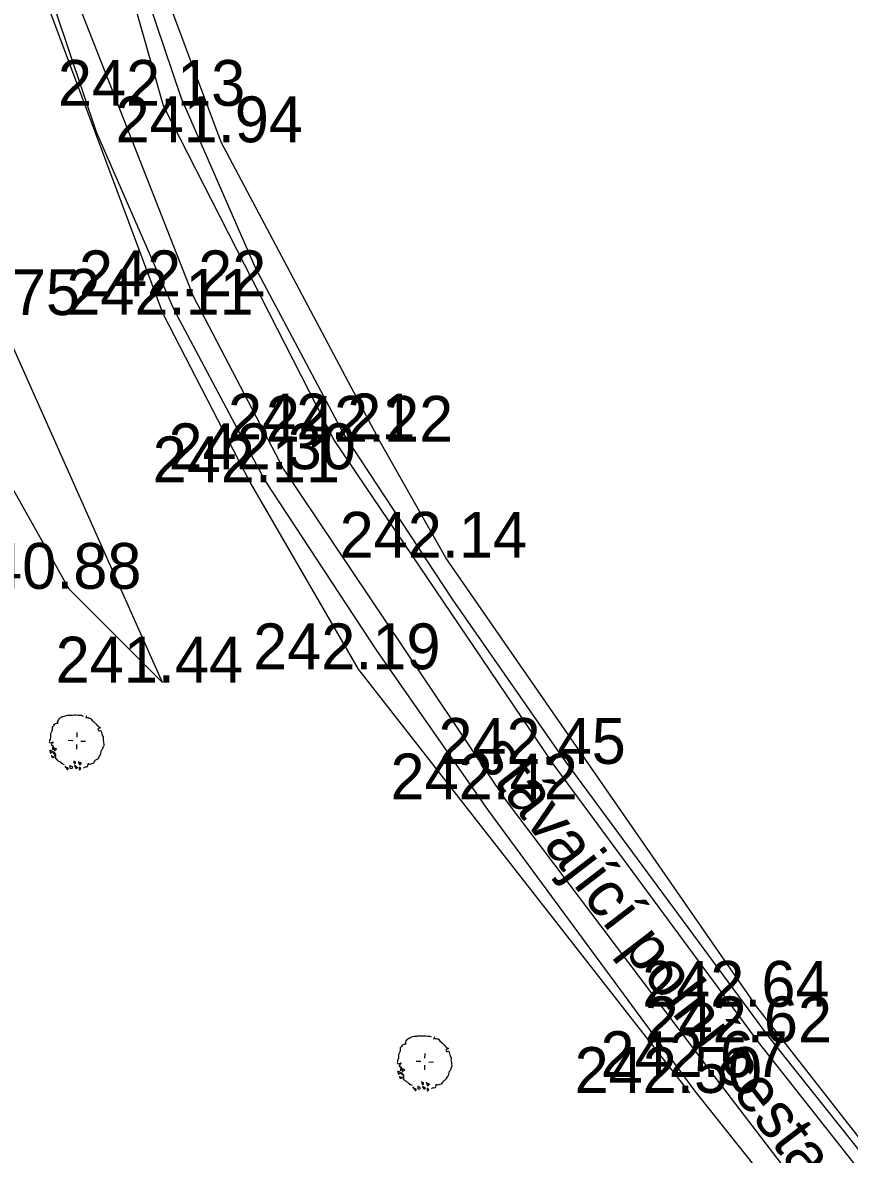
# Model space of a CAD drawing. Extents: x -601739 to -601440, y -1201912 to -1200862.
# Drawn here: x -601509.07 to -601472.98, y -1201685.45 to -1201636.06 of the extents above; entities that cross this region are included whole.
import ezdxf

# ---------------------------------------------------------------- set-up
doc = ezdxf.new("R2010")
doc.units = 0
for name, color, linetype in [('Hranice parcel', 7, 'Continuous'), ('u_hrany', 7, 'Continuous'), ('u_S0 02', 7, 'Continuous'), ('u_vysadba', 7, 'Continuous'), ('u_vyska', 7, 'Continuous')]:
    doc.layers.add(name, color=color, linetype=linetype)

msp = doc.modelspace()

# ---------------------------------------------------------------- linework, layer by layer
at = {"layer": 'Hranice parcel'}
for points in [[(-601518.5, -1201574.62), (-601510.22, -1201581.07), (-601510.94, -1201612.53), (-601510.72, -1201619.53), (-601510.05, -1201624.75), (-601508.24, -1201633.75), (-601505.86, -1201640.82), (-601502.47, -1201648.58), (-601498.5, -1201656.04), (-601493.62, -1201663.46), (-601488.75, -1201670.45), (-601479.72, -1201682.69), (-601461.88, -1201705.09), (-601445.87, -1201723.83)], [(-601460.43, -1201700.48), (-601476.54, -1201680.26), (-601485.5, -1201668.12), (-601490.31, -1201661.22), (-601495.06, -1201653.99), (-601498.9, -1201646.76), (-601502.13, -1201639.37), (-601504.35, -1201632.81), (-601505.66, -1201626.3)]]:
    msp.add_lwpolyline(points, dxfattribs=at)
at = {"layer": 'u_hrany'}
for points in [[(-601514.2, -1201569.51), (-601517.03, -1201570.93), (-601522.49, -1201584.67), (-601523.6, -1201596.8), (-601523.78, -1201607.28), (-601522.35, -1201622.38), (-601520.26, -1201632.29), (-601514.11, -1201648.21), (-601507.05, -1201660.77), (-601502.96, -1201664.86), (-601510.13, -1201648.82), (-601514.08, -1201638.6), (-601517, -1201627.14), (-601517.98, -1201618.06), (-601518.55, -1201594.5), (-601514.93, -1201583.59), (-601509.76, -1201580.82)], [(-601460.33, -1201700.35), (-601477.02, -1201679.01), (-601490.59, -1201659.41), (-601493.47, -1201654.35), (-601500.4, -1201641.28), (-601502.56, -1201635.52), (-601504.77, -1201626.02), (-601500.77, -1201618.77)], [(-601443.32, -1201721.42), (-601460.41, -1201701.5), (-601476.94, -1201680.56), (-601485.91, -1201668.41), (-601495.49, -1201654.25), (-601502.92, -1201639.69), (-601504.84, -1201632.93)], [(-601502.92, -1201648.81), (-601508.49, -1201633.89)], [(-601507.17, -1201633.88), (-601501.63, -1201648), (-601497.69, -1201655.55), (-601488, -1201669.96), (-601478.86, -1201682.08), (-601462.72, -1201703.16), (-601444.89, -1201723.91)], [(-601502.92, -1201648.81), (-601499.15, -1201656.12), (-601494.42, -1201664.28), (-601479.96, -1201682.77)]]:
    msp.add_lwpolyline(points, dxfattribs=at)
at = {"layer": 'u_vysadba'}
for points in [[(-601507.697, -1201666.71), (-601507.696, -1201666.68), (-601507.636, -1201666.654), (-601507.606, -1201666.641), (-601507.576, -1201666.628), (-601507.546, -1201666.63), (-601507.517, -1201666.631), (-601507.53, -1201666.601), (-601507.543, -1201666.571), (-601507.526, -1201666.528), (-601507.51, -1201666.485), (-601507.478, -1201666.443), (-601507.447, -1201666.415), (-601507.417, -1201666.388), (-601507.371, -1201666.361), (-601507.327, -1201666.363), (-601507.297, -1201666.335), (-601507.222, -1201666.31), (-601507.163, -1201666.299), (-601507.118, -1201666.286), (-601507.06, -1201666.289), (-601507.015, -1201666.277), (-601506.972, -1201666.279), (-601506.899, -1201666.283), (-601506.825, -1201666.272), (-601506.752, -1201666.276), (-601506.664, -1201666.281), (-601506.577, -1201666.286), (-601506.504, -1201666.289), (-601506.46, -1201666.306), (-601506.432, -1201666.322)], [(-601506.285, -1201666.316), (-601506.301, -1201666.344), (-601506.303, -1201666.373), (-601506.319, -1201666.402), (-601506.275, -1201666.389), (-601506.245, -1201666.391), (-601506.216, -1201666.392), (-601506.173, -1201666.409), (-601506.129, -1201666.412), (-601506.087, -1201666.443), (-601506.059, -1201666.474), (-601506.032, -1201666.519), (-601505.99, -1201666.551), (-601505.934, -1201666.598), (-601505.893, -1201666.644), (-601505.865, -1201666.675), (-601505.824, -1201666.735), (-601505.767, -1201666.768), (-601505.725, -1201666.799), (-601505.682, -1201666.816), (-601505.684, -1201666.845)], [(-601507.697, -1201666.71), (-601507.698, -1201666.724), (-601507.744, -1201666.766), (-601507.775, -1201666.793), (-601507.777, -1201666.837), (-601507.779, -1201666.881), (-601507.782, -1201666.939), (-601507.799, -1201666.982), (-601507.816, -1201667.011), (-601507.832, -1201667.039), (-601507.849, -1201667.097), (-601507.851, -1201667.126), (-601507.854, -1201667.184), (-601507.856, -1201667.228), (-601507.858, -1201667.258), (-601507.876, -1201667.33), (-601507.893, -1201667.373), (-601507.896, -1201667.417), (-601507.912, -1201667.445), (-601507.899, -1201667.475), (-601507.856, -1201667.492), (-601507.766, -1201667.467), (-601507.736, -1201667.454), (-601507.769, -1201667.511), (-601507.8, -1201667.539), (-601507.816, -1201667.567), (-601507.818, -1201667.611), (-601507.789, -1201667.613), (-601507.745, -1201667.615), (-601507.732, -1201667.645), (-601507.749, -1201667.688), (-601507.765, -1201667.716), (-601507.767, -1201667.76), (-601507.77, -1201667.804)], [(-601506.698, -1201667.251), (-601506.687, -1201667.047)], [(-601505.684, -1201666.845), (-601505.728, -1201666.858), (-601505.773, -1201666.87), (-601505.789, -1201666.898), (-601505.776, -1201666.928), (-601505.749, -1201666.974), (-601505.719, -1201666.961), (-601505.674, -1201666.948), (-601505.647, -1201666.979), (-601505.634, -1201667.009), (-601505.635, -1201667.038), (-601505.609, -1201667.098), (-601505.597, -1201667.143), (-601505.585, -1201667.187), (-601505.558, -1201667.233), (-601505.559, -1201667.262), (-601505.561, -1201667.306), (-601505.563, -1201667.335), (-601505.551, -1201667.379), (-601505.539, -1201667.439), (-601505.542, -1201667.497), (-601505.531, -1201667.556), (-601505.532, -1201667.585), (-601505.534, -1201667.615), (-601505.536, -1201667.658), (-601505.567, -1201667.686), (-601505.568, -1201667.715), (-601505.585, -1201667.758), (-601505.602, -1201667.787), (-601505.648, -1201667.828), (-601505.651, -1201667.887), (-601505.668, -1201667.944), (-601505.687, -1201668.016), (-601505.734, -1201668.073), (-601505.767, -1201668.144), (-601505.799, -1201668.201), (-601505.859, -1201668.227), (-601505.89, -1201668.255), (-601505.936, -1201668.296), (-601505.967, -1201668.338), (-601505.984, -1201668.381), (-601506.044, -1201668.408), (-601506.089, -1201668.42), (-601506.119, -1201668.433), (-601506.162, -1201668.416), (-601506.205, -1201668.399), (-601506.222, -1201668.442), (-601506.24, -1201668.5), (-601506.256, -1201668.543), (-601506.301, -1201668.555), (-601506.345, -1201668.553)], [(-601506.881, -1201667.402), (-601507.086, -1201667.392)], [(-601506.714, -1201667.558), (-601506.725, -1201667.762)], [(-601506.531, -1201667.421), (-601506.326, -1201667.417)], [(-601507.901, -1201667.797), (-601507.888, -1201667.827), (-601507.876, -1201667.872), (-601507.863, -1201667.902), (-601507.864, -1201667.931), (-601507.836, -1201667.947), (-601507.805, -1201667.919), (-601507.759, -1201667.878), (-601507.788, -1201667.876), (-601507.83, -1201667.845), (-601507.873, -1201667.828)], [(-601507.811, -1201668.036), (-601507.801, -1201668.124), (-601507.757, -1201668.127), (-601507.728, -1201668.128), (-601507.684, -1201668.116), (-601507.741, -1201668.098), (-601507.785, -1201668.096), (-601507.798, -1201668.066)], [(-601507.743, -1201667.864), (-601507.702, -1201667.91), (-601507.66, -1201667.956), (-601507.618, -1201667.988)], [(-601507.618, -1201667.988), (-601507.647, -1201667.986), (-601507.677, -1201667.985), (-601507.706, -1201667.983), (-601507.719, -1201667.953), (-601507.717, -1201667.924), (-601507.73, -1201667.894)], [(-601507.719, -1201667.675), (-601507.721, -1201667.719), (-601507.708, -1201667.749), (-601507.696, -1201667.793), (-601507.683, -1201667.823), (-601507.654, -1201667.825), (-601507.637, -1201667.796), (-601507.577, -1201667.77), (-601507.62, -1201667.753), (-601507.649, -1201667.737), (-601507.706, -1201667.705)], [(-601507.247, -1201668.447), (-601507.29, -1201668.43), (-601507.319, -1201668.413), (-601507.348, -1201668.412), (-601507.375, -1201668.367), (-601507.403, -1201668.35), (-601507.445, -1201668.319), (-601507.488, -1201668.302), (-601507.53, -1201668.256), (-601507.558, -1201668.225), (-601507.629, -1201668.192), (-601507.627, -1201668.148), (-601507.624, -1201668.104), (-601507.637, -1201668.074), (-601507.666, -1201668.058), (-601507.634, -1201668.016), (-601507.605, -1201668.018)], [(-601507.236, -1201668.506), (-601507.14, -1201668.628), (-601507.113, -1201668.673), (-601507.081, -1201668.631), (-601507.08, -1201668.602), (-601507.108, -1201668.586), (-601507.151, -1201668.569), (-601507.18, -1201668.553), (-601507.208, -1201668.536)], [(-601507.013, -1201668.459), (-601507.017, -1201668.532), (-601507.005, -1201668.576), (-601506.977, -1201668.607), (-601506.918, -1201668.596), (-601506.887, -1201668.568), (-601506.901, -1201668.538), (-601506.944, -1201668.521), (-601506.987, -1201668.504)], [(-601506.843, -1201668.278), (-601506.832, -1201668.351), (-601506.805, -1201668.397), (-601506.761, -1201668.384), (-601506.759, -1201668.355), (-601506.758, -1201668.326), (-601506.801, -1201668.309), (-601506.829, -1201668.293)], [(-601506.808, -1201668.455), (-601506.725, -1201668.533), (-601506.696, -1201668.549), (-601506.683, -1201668.579), (-601506.714, -1201668.606), (-601506.743, -1201668.605), (-601506.756, -1201668.575), (-601506.783, -1201668.53), (-601506.811, -1201668.499)], [(-601506.64, -1201668.318), (-601506.614, -1201668.377), (-601506.602, -1201668.422), (-601506.574, -1201668.453), (-601506.544, -1201668.44), (-601506.512, -1201668.397), (-601506.511, -1201668.368), (-601506.555, -1201668.366), (-601506.583, -1201668.35), (-601506.612, -1201668.334), (-601506.641, -1201668.332)], [(-601506.609, -1201668.568), (-601506.599, -1201668.642), (-601506.585, -1201668.672), (-601506.555, -1201668.659), (-601506.524, -1201668.617), (-601506.552, -1201668.586), (-601506.58, -1201668.57), (-601506.609, -1201668.568)], [(-601506.345, -1201668.553), (-601506.389, -1201668.565), (-601506.42, -1201668.593)], [(-601492.506, -1201680.711), (-601492.505, -1201680.682), (-601492.445, -1201680.656), (-601492.415, -1201680.643), (-601492.385, -1201680.63), (-601492.356, -1201680.632), (-601492.326, -1201680.633), (-601492.339, -1201680.603), (-601492.352, -1201680.573), (-601492.336, -1201680.53), (-601492.319, -1201680.487), (-601492.287, -1201680.445), (-601492.256, -1201680.417), (-601492.226, -1201680.39), (-601492.18, -1201680.363), (-601492.136, -1201680.365), (-601492.106, -1201680.337), (-601492.031, -1201680.312), (-601491.972, -1201680.3), (-601491.927, -1201680.288), (-601491.869, -1201680.291), (-601491.824, -1201680.279), (-601491.781, -1201680.281), (-601491.708, -1201680.285), (-601491.634, -1201680.274), (-601491.561, -1201680.278), (-601491.473, -1201680.283), (-601491.386, -1201680.287), (-601491.313, -1201680.291), (-601491.27, -1201680.308), (-601491.241, -1201680.324)], [(-601491.094, -1201680.318), (-601491.111, -1201680.346), (-601491.112, -1201680.375), (-601491.128, -1201680.404), (-601491.084, -1201680.391), (-601491.054, -1201680.393), (-601491.025, -1201680.394), (-601490.982, -1201680.411), (-601490.938, -1201680.414), (-601490.896, -1201680.445), (-601490.868, -1201680.476), (-601490.842, -1201680.521), (-601490.799, -1201680.553), (-601490.743, -1201680.6), (-601490.702, -1201680.646), (-601490.674, -1201680.676), (-601490.633, -1201680.737), (-601490.576, -1201680.77), (-601490.534, -1201680.801), (-601490.491, -1201680.818), (-601490.493, -1201680.847)], [(-601492.506, -1201680.711), (-601492.507, -1201680.726), (-601492.553, -1201680.768), (-601492.584, -1201680.795), (-601492.586, -1201680.839), (-601492.588, -1201680.883), (-601492.592, -1201680.941), (-601492.608, -1201680.984), (-601492.625, -1201681.013), (-601492.641, -1201681.041), (-601492.658, -1201681.099), (-601492.66, -1201681.128), (-601492.663, -1201681.186), (-601492.665, -1201681.23), (-601492.667, -1201681.259), (-601492.685, -1201681.332), (-601492.702, -1201681.375), (-601492.705, -1201681.418), (-601492.721, -1201681.447), (-601492.708, -1201681.477), (-601492.665, -1201681.494), (-601492.576, -1201681.469), (-601492.546, -1201681.456), (-601492.578, -1201681.513), (-601492.609, -1201681.541), (-601492.625, -1201681.569), (-601492.627, -1201681.613), (-601492.598, -1201681.614), (-601492.554, -1201681.617), (-601492.541, -1201681.647), (-601492.558, -1201681.69), (-601492.574, -1201681.718), (-601492.576, -1201681.762), (-601492.579, -1201681.806)], [(-601490.493, -1201680.847), (-601490.537, -1201680.859), (-601490.582, -1201680.872), (-601490.598, -1201680.9), (-601490.585, -1201680.93), (-601490.558, -1201680.975), (-601490.528, -1201680.962), (-601490.484, -1201680.95), (-601490.456, -1201680.981), (-601490.443, -1201681.011), (-601490.444, -1201681.04), (-601490.418, -1201681.1), (-601490.406, -1201681.145), (-601490.394, -1201681.189), (-601490.367, -1201681.235), (-601490.368, -1201681.264), (-601490.371, -1201681.308), (-601490.372, -1201681.337), (-601490.36, -1201681.381), (-601490.348, -1201681.44), (-601490.351, -1201681.499), (-601490.34, -1201681.558), (-601490.341, -1201681.587), (-601490.343, -1201681.616), (-601490.345, -1201681.66), (-601490.376, -1201681.688), (-601490.378, -1201681.717), (-601490.395, -1201681.76), (-601490.411, -1201681.789), (-601490.457, -1201681.83), (-601490.46, -1201681.889), (-601490.478, -1201681.946), (-601490.496, -1201682.018), (-601490.543, -1201682.074), (-601490.576, -1201682.146), (-601490.608, -1201682.203), (-601490.668, -1201682.229), (-601490.699, -1201682.257), (-601490.745, -1201682.298), (-601490.777, -1201682.34), (-601490.794, -1201682.383), (-601490.853, -1201682.409), (-601490.898, -1201682.422), (-601490.928, -1201682.435), (-601490.971, -1201682.418), (-601491.014, -1201682.401), (-601491.031, -1201682.444), (-601491.049, -1201682.502), (-601491.066, -1201682.545), (-601491.11, -1201682.557), (-601491.154, -1201682.555)], [(-601491.507, -1201681.253), (-601491.496, -1201681.049)], [(-601492.71, -1201681.799), (-601492.697, -1201681.829), (-601492.685, -1201681.873), (-601492.672, -1201681.903), (-601492.673, -1201681.933), (-601492.645, -1201681.949), (-601492.614, -1201681.921), (-601492.568, -1201681.88), (-601492.597, -1201681.878), (-601492.639, -1201681.847), (-601492.682, -1201681.83)], [(-601492.553, -1201681.866), (-601492.511, -1201681.912), (-601492.47, -1201681.958), (-601492.427, -1201681.99)], [(-601492.528, -1201681.677), (-601492.53, -1201681.721), (-601492.517, -1201681.751), (-601492.505, -1201681.795), (-601492.492, -1201681.825), (-601492.463, -1201681.827), (-601492.446, -1201681.798), (-601492.387, -1201681.772), (-601492.43, -1201681.755), (-601492.458, -1201681.739), (-601492.515, -1201681.707)], [(-601491.69, -1201681.404), (-601491.895, -1201681.394)], [(-601491.523, -1201681.56), (-601491.534, -1201681.764)], [(-601491.34, -1201681.423), (-601491.135, -1201681.419)], [(-601492.62, -1201682.038), (-601492.61, -1201682.126), (-601492.566, -1201682.129), (-601492.537, -1201682.13), (-601492.493, -1201682.118), (-601492.55, -1201682.1), (-601492.594, -1201682.098), (-601492.607, -1201682.068)], [(-601492.427, -1201681.99), (-601492.457, -1201681.988), (-601492.486, -1201681.986), (-601492.515, -1201681.985), (-601492.528, -1201681.955), (-601492.526, -1201681.926), (-601492.54, -1201681.896)], [(-601492.056, -1201682.448), (-601492.099, -1201682.432), (-601492.128, -1201682.415), (-601492.157, -1201682.414), (-601492.184, -1201682.368), (-601492.212, -1201682.352), (-601492.254, -1201682.321), (-601492.298, -1201682.304), (-601492.339, -1201682.258), (-601492.367, -1201682.227), (-601492.438, -1201682.194), (-601492.436, -1201682.15), (-601492.433, -1201682.106), (-601492.447, -1201682.076), (-601492.475, -1201682.06), (-601492.443, -1201682.018), (-601492.414, -1201682.02)], [(-601491.652, -1201682.279), (-601491.641, -1201682.353), (-601491.614, -1201682.399), (-601491.57, -1201682.386), (-601491.568, -1201682.357), (-601491.567, -1201682.328), (-601491.61, -1201682.311), (-601491.638, -1201682.295)], [(-601491.449, -1201682.319), (-601491.423, -1201682.379), (-601491.411, -1201682.424), (-601491.383, -1201682.455), (-601491.353, -1201682.442), (-601491.321, -1201682.399), (-601491.32, -1201682.37), (-601491.364, -1201682.368), (-601491.392, -1201682.352), (-601491.421, -1201682.336), (-601491.45, -1201682.334)], [(-601492.045, -1201682.508), (-601491.949, -1201682.63), (-601491.922, -1201682.675), (-601491.89, -1201682.633), (-601491.889, -1201682.604), (-601491.917, -1201682.588), (-601491.96, -1201682.571), (-601491.989, -1201682.555), (-601492.017, -1201682.538)], [(-601491.823, -1201682.461), (-601491.826, -1201682.534), (-601491.814, -1201682.578), (-601491.786, -1201682.609), (-601491.727, -1201682.598), (-601491.697, -1201682.57), (-601491.71, -1201682.54), (-601491.753, -1201682.523), (-601491.796, -1201682.506)], [(-601491.617, -1201682.457), (-601491.534, -1201682.535), (-601491.505, -1201682.551), (-601491.492, -1201682.581), (-601491.523, -1201682.608), (-601491.552, -1201682.607), (-601491.565, -1201682.577), (-601491.592, -1201682.532), (-601491.62, -1201682.501)], [(-601491.418, -1201682.57), (-601491.408, -1201682.644), (-601491.395, -1201682.674), (-601491.365, -1201682.661), (-601491.333, -1201682.618), (-601491.361, -1201682.588), (-601491.389, -1201682.572), (-601491.418, -1201682.57)], [(-601491.154, -1201682.555), (-601491.199, -1201682.567), (-601491.229, -1201682.595)]]:
    msp.add_lwpolyline(points, dxfattribs=at)

# ---------------------------------------------------------------- texts
at = {"layer": 'u_S0 02'}
msp.add_text('stávající polní cesta ', height=2, rotation=307.4888, dxfattribs=at).set_placement((-601489.357, -1201668.078))
at = {"layer": 'u_vyska'}
for s, p in [('242.13', (-601507.533, -1201639.69)), ('241.94', (-601505.016, -1201641.28)), ('242.22', (-601506.614, -1201648)), ('241.75', (-601514.748, -1201648.82)), ('242.11', (-601507.164, -1201648.81)), ('242.21', (-601500.105, -1201654.25)), ('242.22', (-601498.454, -1201654.35)), ('242.30', (-601502.705, -1201655.55)), ('242.11', (-601503.394, -1201656.12)), ('242.14', (-601495.231, -1201659.41)), ('240.88', (-601512.065, -1201660.77)), ('242.19', (-601499.009, -1201664.28)), ('241.44', (-601507.629, -1201664.86)), ('242.45', (-601490.922, -1201668.41)), ('242.42', (-601493.012, -1201669.96)), ('242.64', (-601482.027, -1201679.01)), ('242.62', (-601481.919, -1201680.56)), ('242.67', (-601483.844, -1201682.08)), ('242.50', (-601484.975, -1201682.77))]:
    msp.add_text(s, height=2, dxfattribs=at).set_placement(p)

doc.saveas('drawing.dxf')
